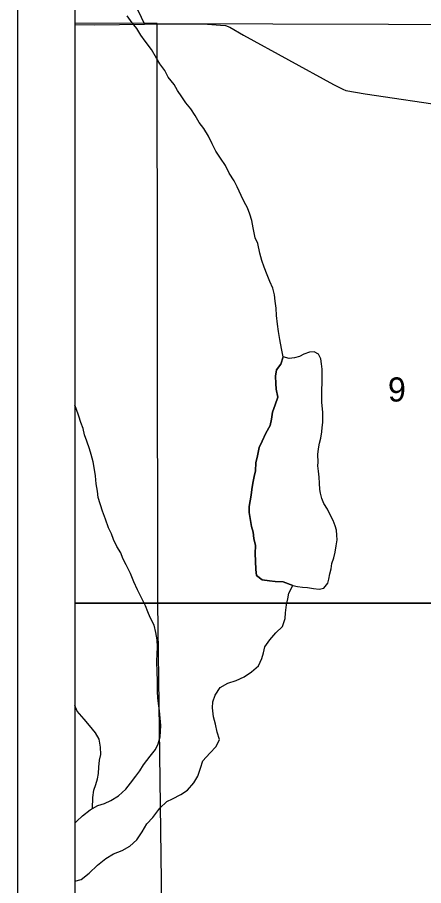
# Model space of a CAD drawing. Extents: x 0 to 34, y 0 to 22.
# Drawn here: x 2 to 2.706, y 15.037 to 16.545 of the extents above; entities that cross this region are included whole.
import ezdxf

# ---------------------------------------------------------------- set-up
doc = ezdxf.new("R2010")
doc.units = 0
for name, color, linetype in [('Default', 7, 'Continuous'), ('SH_Cut_Line', 7, 'Continuous'), ('SH_Data', 7, 'Continuous')]:
    doc.layers.add(name, color=color, linetype=linetype)

msp = doc.modelspace()

# ---------------------------------------------------------------- linework, layer by layer
at = {"layer": 'Default'}
for points in [[(2.1, 17.0156), (2.1, 14.1), (6.2892, 14.1), (6.2892, 14.18), (6.2889, 14.4906), (6.2926, 14.8972), (6.2959, 15.2705), (6.2922, 16.0152), (6.2871, 17.0188)], [(2.1, 16.7319), (2.1118, 16.7185), (2.1371, 16.6845), (2.1653, 16.6387), (2.1912, 16.597), (2.2208, 16.5334)], [(2.3163, 16.3625), (2.3093, 16.3749), (2.3015, 16.3865), (2.2931, 16.3966), (2.2857, 16.4071), (2.2787, 16.4184), (2.2729, 16.4285), (2.2621, 16.4412), (2.2566, 16.4529), (2.2477, 16.4645), (2.2419, 16.4743), (2.2333, 16.4897), (2.2225, 16.5039), (2.2148, 16.5144), (2.2078, 16.526), (2.1997, 16.5361), (2.1908, 16.5477)], [(2.1, 16.5331), (2.1344, 16.5325), (2.2208, 16.5334), (2.2952, 16.5341), (2.3308, 16.5333), (2.3532, 16.5318), (2.3617, 16.531), (2.3692, 16.5283), (2.393, 16.5144), (2.5498, 16.4286), (2.566, 16.4206), (2.5709, 16.418), (2.6047, 16.4125), (2.7536, 16.3903)], [(2.2957, 15.2024), (2.3069, 15.2151), (2.3139, 15.227), (2.3182, 15.2407), (2.3225, 15.2537), (2.3347, 15.2668), (2.3459, 15.2783), (2.3514, 15.2905), (2.3474, 15.3034), (2.3445, 15.317), (2.3409, 15.3302), (2.3395, 15.3453), (2.3401, 15.3559), (2.3437, 15.3678), (2.3529, 15.3808), (2.366, 15.3886), (2.3807, 15.393), (2.3942, 15.3993), (2.4073, 15.4079), (2.4192, 15.4183), (2.425, 15.4313), (2.4279, 15.4412), (2.43, 15.4514), (2.4392, 15.4637), (2.4496, 15.476), (2.4608, 15.4868), (2.4654, 15.5009), (2.466, 15.5104), (2.4677, 15.5245), (2.4702, 15.5351), (2.4719, 15.545), (2.4792, 15.558), (2.4621, 15.5646), (2.4485, 15.5651), (2.4383, 15.5665), (2.4258, 15.5682), (2.4155, 15.5756), (2.4149, 15.5862), (2.4139, 15.6002), (2.4137, 15.6135), (2.4138, 15.6279), (2.4114, 15.64), (2.4101, 15.6506), (2.4069, 15.6607), (2.4048, 15.6747), (2.4031, 15.6849), (2.4033, 15.6952), (2.405, 15.7054), (2.4064, 15.7149), (2.4077, 15.7252), (2.4094, 15.7358), (2.4115, 15.7473), (2.414, 15.7572), (2.4145, 15.7712), (2.4173, 15.7834), (2.4205, 15.7982), (2.4256, 15.8089), (2.4318, 15.8227), (2.4395, 15.8364), (2.4416, 15.8471), (2.4437, 15.8592), (2.448, 15.8722), (2.4531, 15.8856), (2.4498, 15.8991), (2.4493, 15.9094), (2.4491, 15.9219), (2.4504, 15.9329), (2.4582, 15.9429), (2.4621, 15.9555), (2.4592, 15.9702), (2.4563, 15.9853), (2.4542, 15.9993), (2.4521, 16.0125), (2.4507, 16.0273), (2.4498, 16.0402), (2.4484, 16.0519), (2.4471, 16.0633), (2.4443, 16.0746), (2.4392, 16.0866), (2.4344, 16.0979), (2.4293, 16.1115), (2.425, 16.1228), (2.4217, 16.1356), (2.418, 16.1523), (2.4133, 16.162), (2.41, 16.1794), (2.4079, 16.1923), (2.404, 16.2032), (2.4004, 16.2141), (2.3945, 16.225), (2.3894, 16.2359), (2.3824, 16.251), (2.3769, 16.2615), (2.3684, 16.2746), (2.3618, 16.2878), (2.3532, 16.3009), (2.3451, 16.3129), (2.3385, 16.3253), (2.3326, 16.3389), (2.3244, 16.3524), (2.3163, 16.3625)], [(2.4792, 15.558), (2.4868, 15.5566), (2.4959, 15.5553), (2.5046, 15.5547), (2.5149, 15.5529), (2.5247, 15.552), (2.533, 15.5532), (2.54, 15.5624), (2.5414, 15.5693), (2.5435, 15.5784), (2.5457, 15.5868), (2.547, 15.5963), (2.5503, 15.6062), (2.5524, 15.6161), (2.5541, 15.6268), (2.5558, 15.6374), (2.5557, 15.6457), (2.5548, 15.6541), (2.5527, 15.662), (2.5492, 15.671), (2.5441, 15.6812), (2.539, 15.6906), (2.5328, 15.7007), (2.5293, 15.7094), (2.5269, 15.7188), (2.526, 15.7249), (2.5251, 15.7358), (2.5249, 15.7465), (2.5236, 15.7567), (2.5227, 15.7658), (2.523, 15.7722), (2.5227, 15.7858), (2.5233, 15.7957), (2.5251, 15.8052), (2.5276, 15.8144), (2.5293, 15.8254), (2.5299, 15.8326), (2.5309, 15.8413), (2.5311, 15.852), (2.531, 15.8595), (2.53, 15.8701), (2.5295, 15.8769), (2.5293, 15.8906), (2.5292, 15.8997), (2.5298, 15.9084), (2.53, 15.916), (2.5297, 15.9338), (2.5288, 15.9433), (2.5276, 15.952), (2.5236, 15.9603), (2.516, 15.9643), (2.5081, 15.9638), (2.4983, 15.9598), (2.4904, 15.9563), (2.4818, 15.9535), (2.4727, 15.9526), (2.4621, 15.9555)], [(2.4621, 15.9555), (2.4582, 15.9429), (2.4504, 15.9329), (2.4491, 15.9219), (2.4493, 15.9094), (2.4498, 15.8991), (2.4531, 15.8856), (2.448, 15.8722), (2.4437, 15.8592), (2.4416, 15.8471), (2.4395, 15.8364), (2.4318, 15.8227), (2.4256, 15.8089), (2.4205, 15.7982), (2.4173, 15.7834), (2.4145, 15.7712), (2.414, 15.7572), (2.4115, 15.7473), (2.4094, 15.7358), (2.4077, 15.7252), (2.4064, 15.7149), (2.405, 15.7054), (2.4033, 15.6952), (2.4031, 15.6849), (2.4048, 15.6747), (2.4069, 15.6607), (2.4101, 15.6506), (2.4114, 15.64), (2.4138, 15.6279), (2.4137, 15.6135), (2.4139, 15.6002), (2.4149, 15.5862), (2.4155, 15.5756), (2.4258, 15.5682), (2.4383, 15.5665), (2.4485, 15.5651), (2.4621, 15.5646), (2.4792, 15.558)], [(2.1, 15.145), (2.1035, 15.1488), (2.1135, 15.1577), (2.1266, 15.1682), (2.1401, 15.176), (2.1514, 15.1796), (2.1626, 15.1843), (2.1757, 15.1929), (2.1887, 15.2044), (2.1969, 15.2144), (2.2058, 15.2267), (2.2132, 15.2363), (2.2191, 15.2463), (2.2309, 15.2616), (2.2402, 15.2732), (2.2449, 15.2831), (2.2485, 15.2953), (2.2487, 15.3048), (2.2493, 15.3146), (2.2483, 15.3275), (2.247, 15.3404), (2.2453, 15.3529), (2.244, 15.3627), (2.2438, 15.3737), (2.2435, 15.3934), (2.2429, 15.4067), (2.2425, 15.4264), (2.2431, 15.4393), (2.2437, 15.4507), (2.2431, 15.4636), (2.241, 15.4764), (2.2381, 15.4893), (2.2311, 15.5024), (2.2271, 15.5126), (2.2228, 15.5227), (2.2154, 15.5378), (2.2091, 15.5506), (2.2025, 15.5645), (2.1966, 15.5792), (2.1891, 15.5939), (2.1833, 15.6048), (2.1797, 15.6146), (2.1727, 15.6258), (2.1672, 15.6382), (2.1637, 15.648), (2.1586, 15.6586), (2.1531, 15.6736), (2.1479, 15.6872), (2.1407, 15.711), (2.1394, 15.7223), (2.1373, 15.7348), (2.1359, 15.7484), (2.1338, 15.7632), (2.1318, 15.773), (2.1285, 15.7855), (2.1253, 15.7956), (2.1206, 15.8088), (2.117, 15.8202), (2.1142, 15.8307), (2.1102, 15.8413), (2.1066, 15.8522), (2.1023, 15.8654), (2.1, 15.8716)], [(2.1304, 15.1704), (2.1315, 15.1895), (2.1332, 15.2024), (2.1365, 15.2123), (2.1393, 15.2222), (2.1411, 15.2317), (2.1416, 15.2424), (2.1429, 15.2549), (2.1451, 15.2644), (2.1448, 15.2773), (2.1423, 15.2909), (2.1361, 15.3022), (2.1253, 15.3149), (2.1161, 15.3257), (2.1041, 15.3396), (2.1, 15.3498)], [(2.1, 15.0442), (2.1108, 15.0473), (2.1246, 15.0582), (2.1395, 15.0721), (2.1541, 15.0837), (2.1672, 15.0919), (2.1822, 15.0974), (2.1953, 15.1052), (2.2076, 15.1164), (2.2168, 15.1302), (2.2253, 15.144), (2.2353, 15.1552), (2.2475, 15.1713), (2.2598, 15.1829), (2.2699, 15.1876), (2.2841, 15.195), (2.2957, 15.2024)]]:
    msp.add_lwpolyline(points, dxfattribs=at)
for points in [[(2.1, 16.5351), (2.1, 15.5275), (2.2442, 15.5273), (2.2428, 16.5348)], [(2.2428, 16.5348), (3.2485, 16.532), (3.2514, 15.5272), (2.2442, 15.5273)], [(2.1, 15.5275), (2.1, 14.5191), (2.2573, 14.5177), (2.2442, 15.5273)], [(3.2514, 15.5272), (3.2648, 14.5009), (2.2573, 14.5177), (2.2442, 15.5273)]]:
    msp.add_lwpolyline(points, close=True, dxfattribs=at)
at = {"layer": 'SH_Cut_Line'}
msp.add_lwpolyline([(2.1, 17.0156), (2.1, 14.1), (8.9, 14.1), (8.9, 17.02)], dxfattribs=at)
at = {"layer": 'SH_Data'}
for p, q in [((2, 21), (2, 14)), ((2.1, 20.9), (2.1, 14.1))]:
    msp.add_line(p, q, dxfattribs=at)

# ---------------------------------------------------------------- texts
at = {"layer": 'Default'}
msp.add_text('9', height=0.0419, rotation=0, dxfattribs=at).set_placement((2.6443, 15.8778))

doc.saveas('drawing.dxf')
